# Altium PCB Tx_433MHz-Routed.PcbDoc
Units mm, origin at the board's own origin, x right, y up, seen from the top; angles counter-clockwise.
Board outline 100 x 50 mm, 4 copper layers (SIGNAL_1, SIGNAL_2, SIGNAL_3, SIGNAL_4), stack 1.58 mm thick; 34 components, 24 nets, 121 pads, 221 vias.
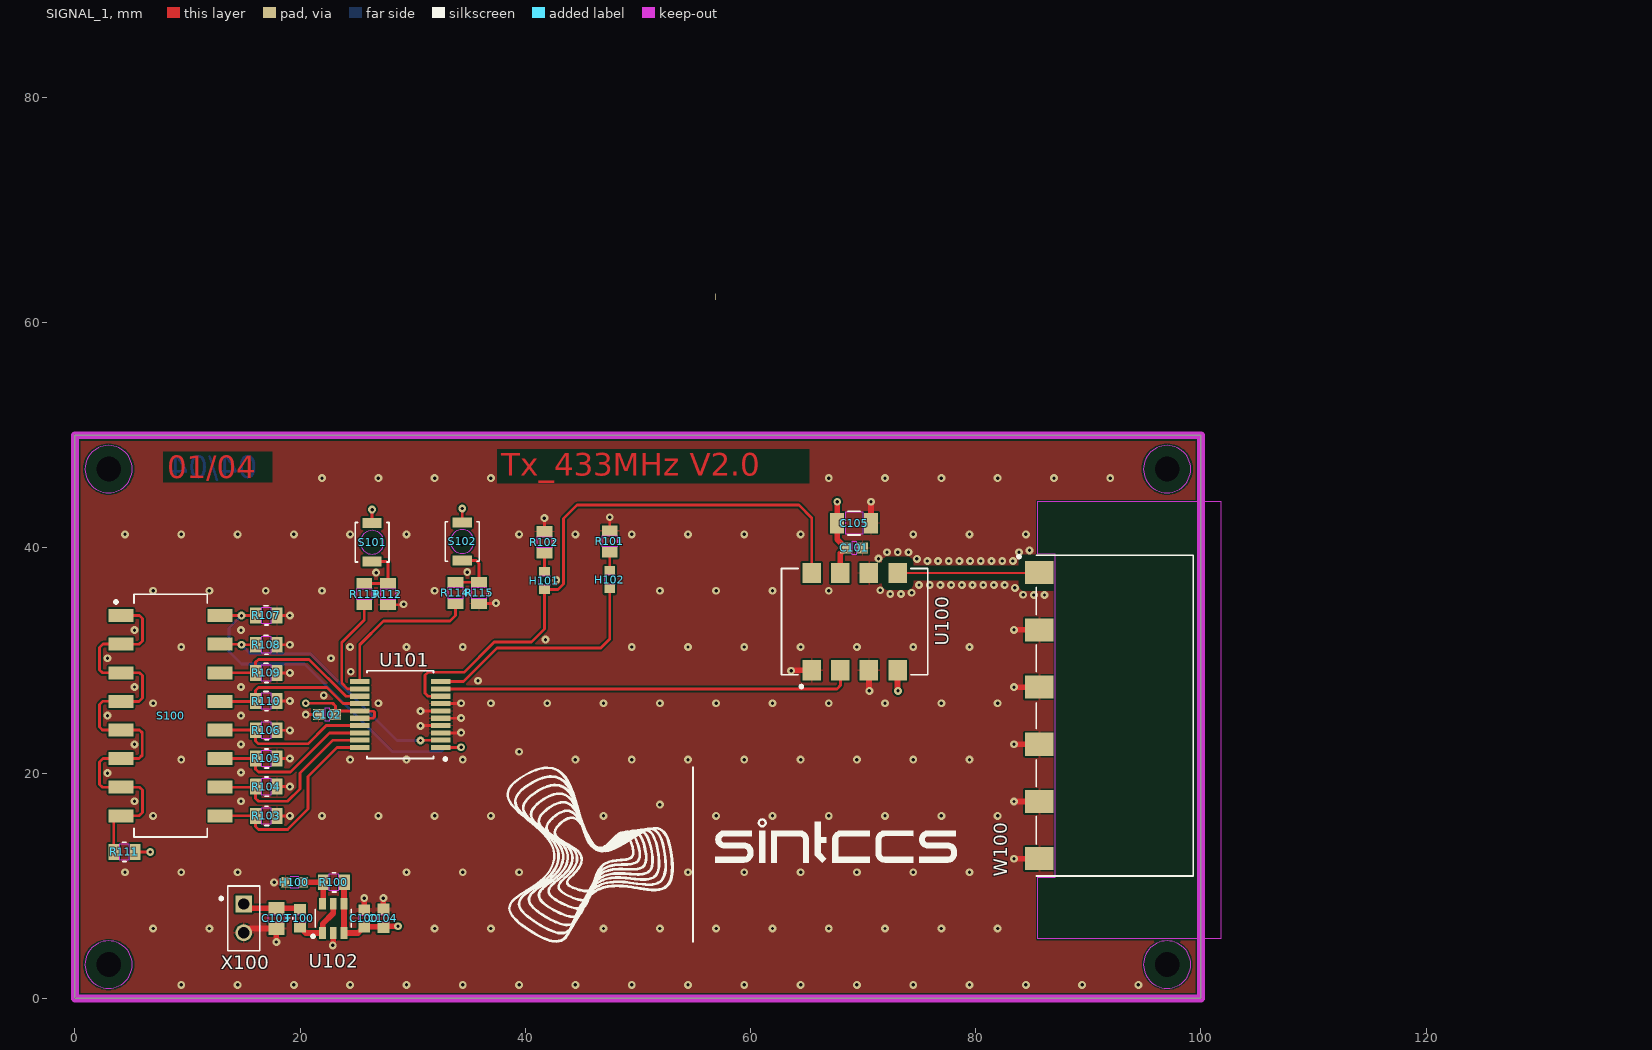
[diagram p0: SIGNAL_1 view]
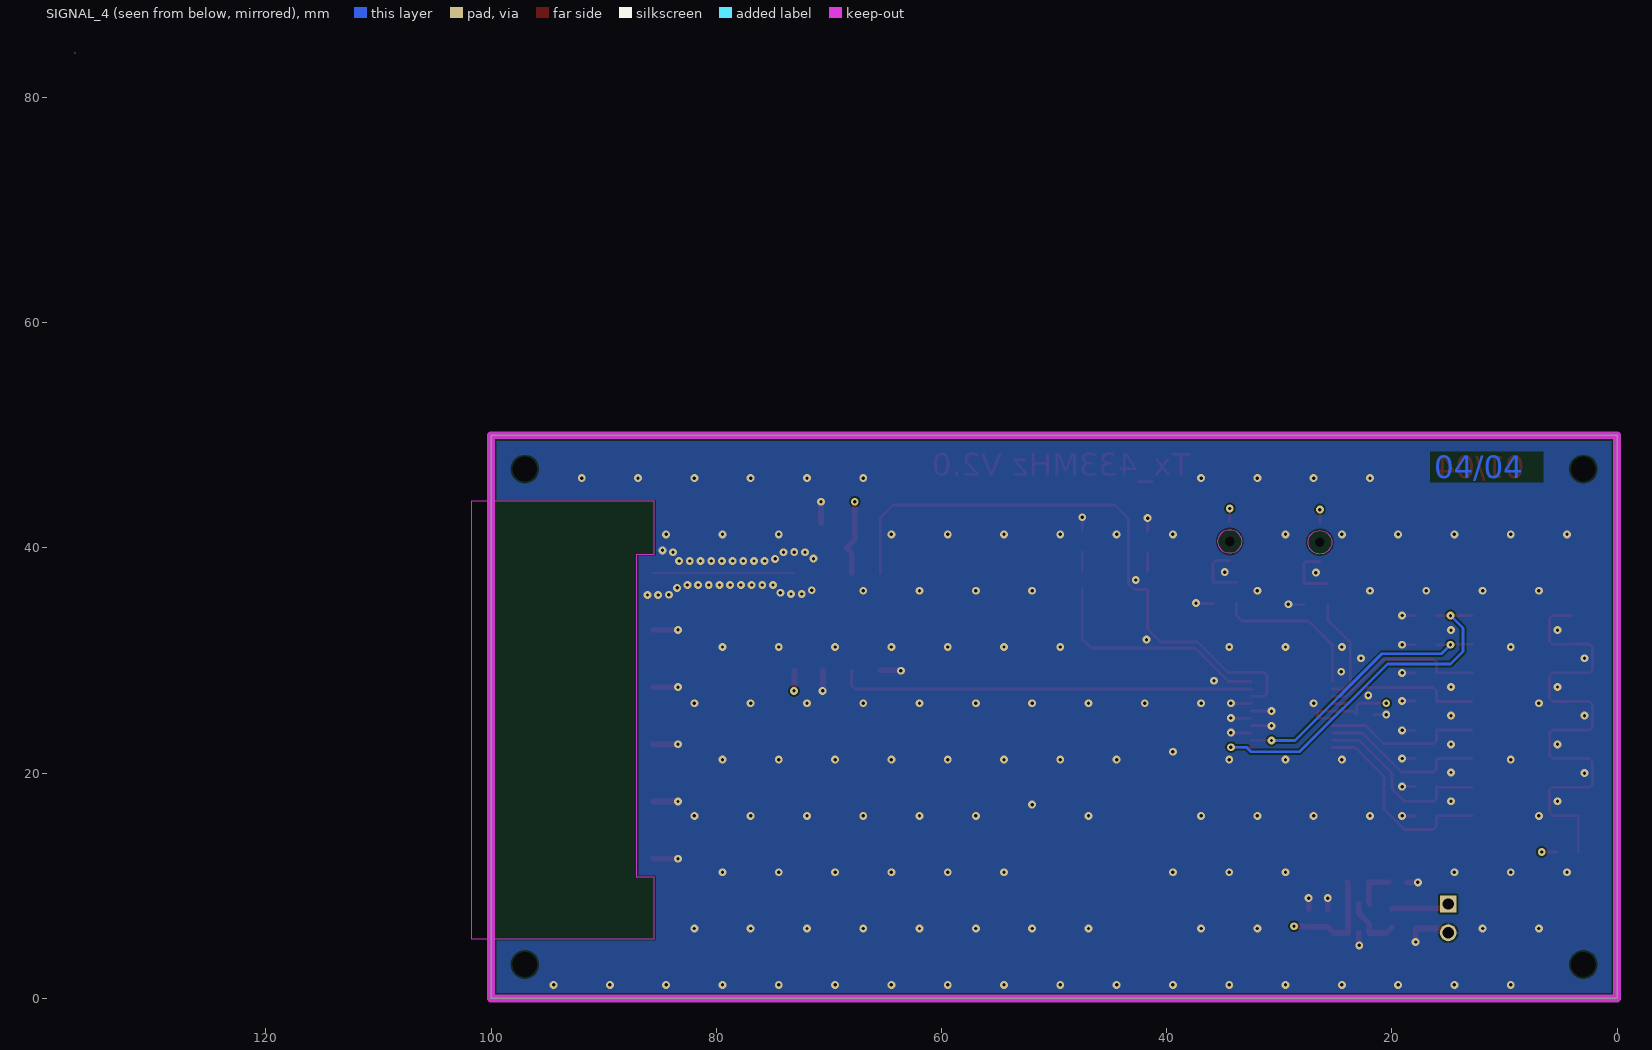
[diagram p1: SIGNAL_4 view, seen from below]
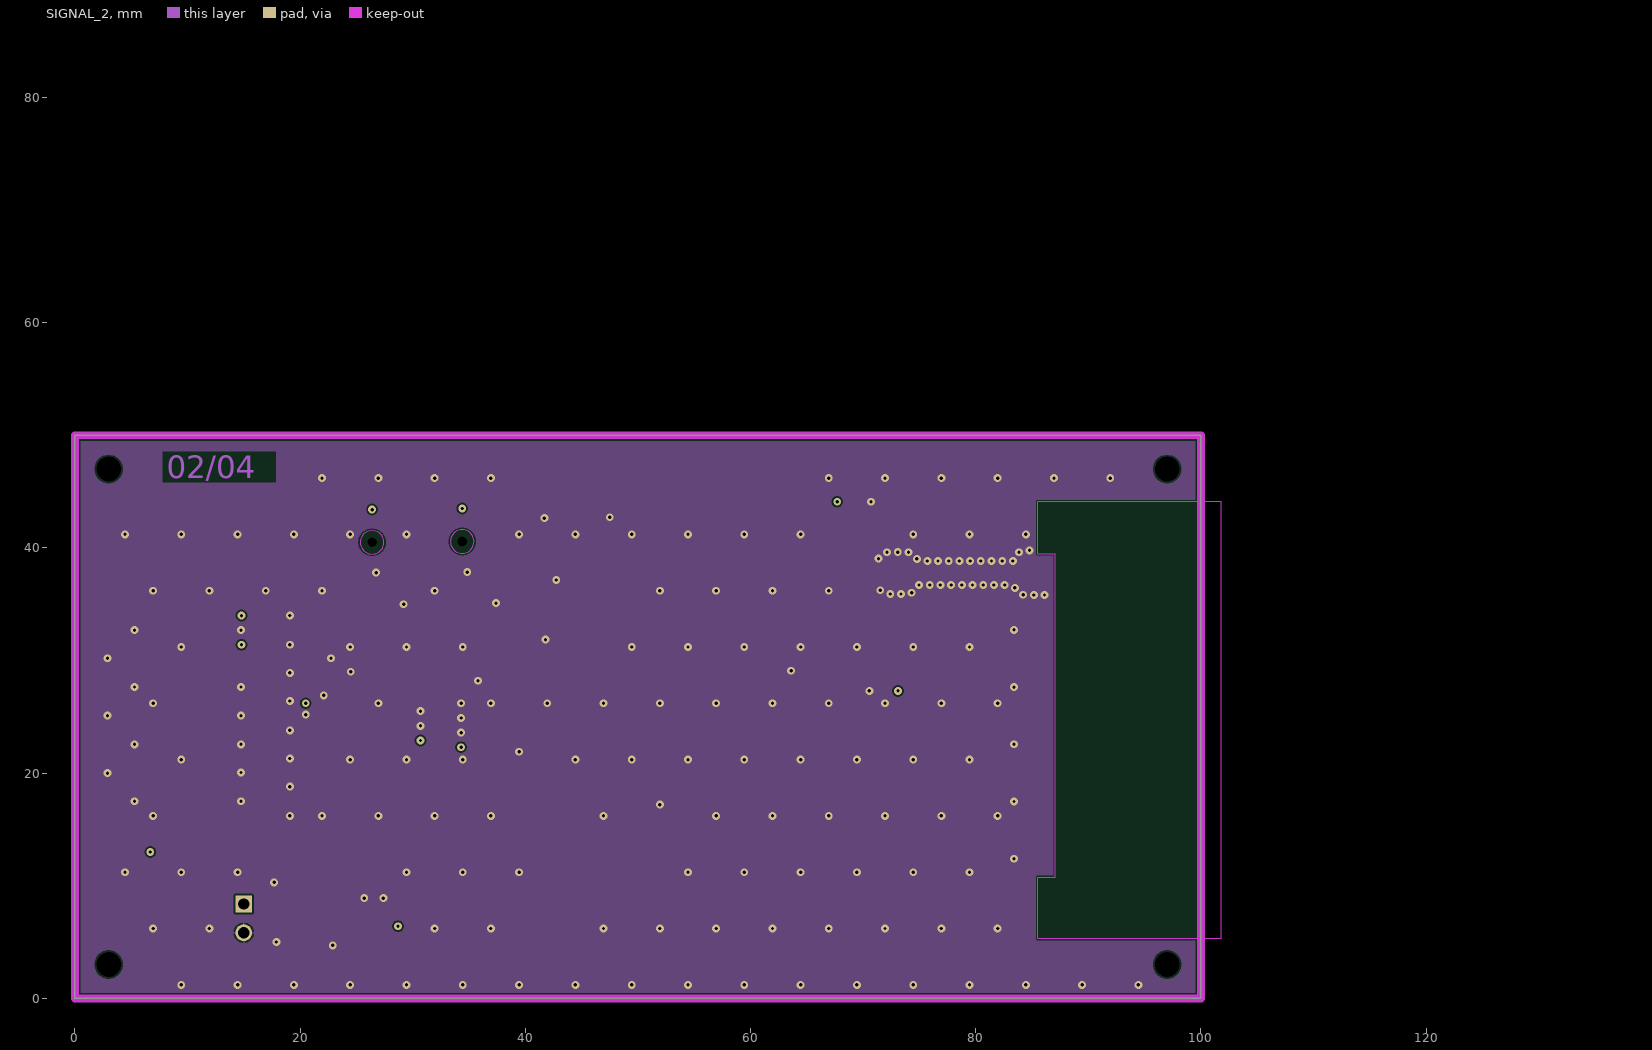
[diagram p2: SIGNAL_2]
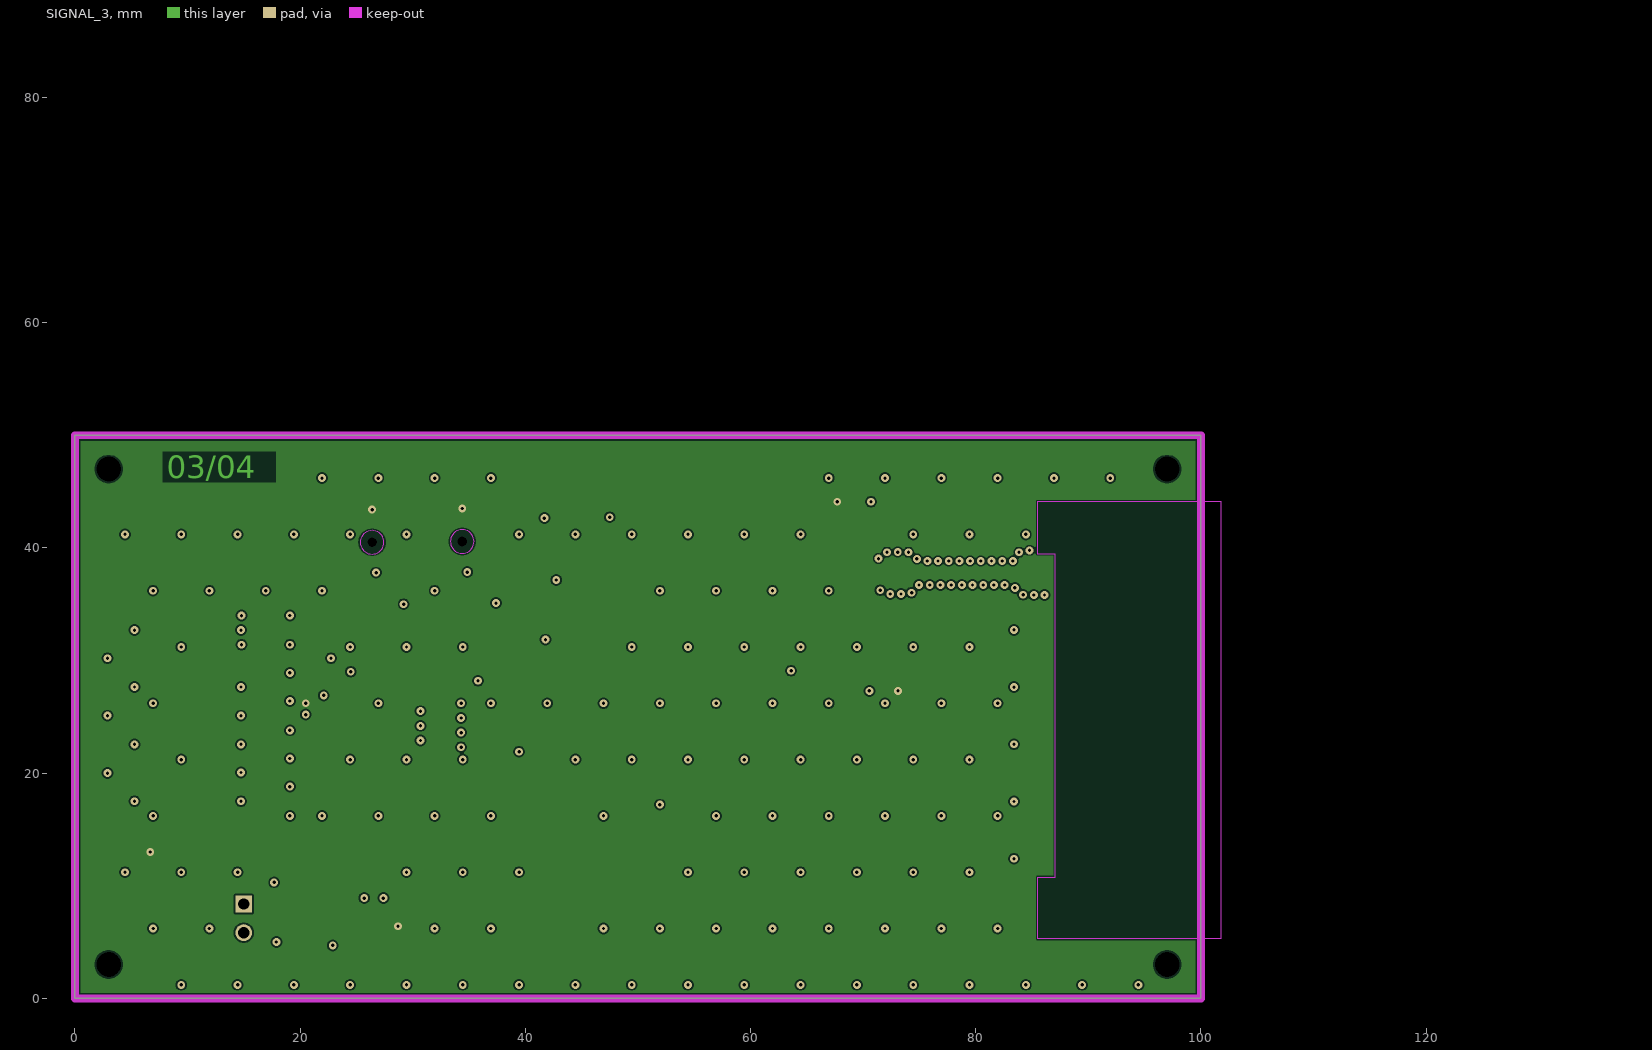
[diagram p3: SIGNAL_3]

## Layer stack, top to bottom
DIELECTRIC_1: solder mask 0.01, Dk 1
SIGNAL_1: signal copper 0.035
DIELECTRIC_3: prepreg 0.12, Dk 4.7
SIGNAL_2: signal copper 0.035
DIELECTRIC_5: prepreg 1.2, Dk 4.7
SIGNAL_3: signal copper 0.035
DIELECTRIC_7: prepreg 0.12, Dk 4.7
SIGNAL_4: signal copper 0.035
DIELECTRIC_9: solder mask 0.01, Dk 1

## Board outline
0,0 0,50 100,50 100,0

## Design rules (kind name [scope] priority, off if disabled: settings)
Clearance Clearance_50R [InNetClass('50R')] p1: gap=0.6 ignorepadtopadclearanceinfootprint=FALSE except(0.2: SMDPad-SMDPad)
Clearance [All] p2: gap=0.15 ignorepadtopadclearanceinfootprint=FALSE
ComponentClearance [All] p1: gap=0.1 collisioncheckmode=3 verticalgap=0.254 showdistances=FALSE
DiffPairsRouting [All] p1: maxlimit=0.254 minlimit=0.254 mostfreqgap=0.254 toplayer_minwidth=0.15 toplayer_maxwidth=0.3 toplayer_prefwidth=0.15 midlayer1_minwidth=0.15 midlayer1_maxwidth=0.3 midlayer1_prefwidth=0.15 midlayer2_minwidth=0.15 midlayer2_maxwidth=0.3 midlayer2_prefwidth=0.15 bottomlayer_minwidth=0.15 bottomlayer_maxwidth=0.3 bottomlayer_prefwidth=0.15 maxuncoupledlength=12.7
MinimumSolderMaskSliver [All] p1: minsoldermaskwidth=0.1
PolygonConnect [All] p1: thpad.connectstyle=Relief thpad.reliefconductorwidth=0.15 thpad.reliefentries=4 thpad.polygonreliefangle="90 Angle" thpad.airgapwidth=0.15 smdpad.connectstyle=Relief smdpad.reliefconductorwidth=0.15 smdpad.reliefentries=4 smdpad.polygonreliefangle="90 Angle" smdpad.airgapwidth=0.15 via.connectstyle=Direct via.reliefconductorwidth=0.127 via.reliefentries=2 via.polygonreliefangle="90 Angle" via.airgapwidth=0.152
RoutingVias [All] p1: holewidth=0.3 width=0.7 viastyle="Through Hole" minholewidth=0.3 minwidth=0.7 maxholewidth=0.3 maxwidth=0.7
SilkToSilkClearance [All] p1: silktosilkclearance=0.1
SolderMaskExpansion SolderMaskExpansion_Via [IsVia] p1: expansion=0.075 istentingtop=FALSE soldermaskfromhole=TRUE
SolderMaskExpansion [All] p2: expansion=0.1 istentingtop=FALSE
SupplyNets "Schematic Supply Nets_1" [InNet('GND_TX')] p1: voltage=0.000
SupplyNets "Schematic Supply Nets" [InNet('3V3_TX')] p2: voltage=0.000
UnRoutedNet [All] p1: checkbadconnections=TRUE
Width "Width for 50E_SE" [InNetClass('50R')] p1: maxlimit=0.2 minlimit=0.185 preferedwidth=0.2 toplayer_minwidth=0.2 bottomlayer_minwidth=0.2 impedanceprofiledriven=TRUE impedanceprofileid={877E34D1-77DC-4DEE-A0FB-207FE4FBDA97} impedanceprofilevalue=50.000000 minimp=50.000000 maximp=50.000000 favimp=50.000000
Width [All] p2: maxlimit=1 minlimit=0.15 preferedwidth=0.2
25 further rules are at their usual default settings.

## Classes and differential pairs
net class 50R: RF_TX
polygon class "\"(Inherited)\"": GND_RX_L02_P002

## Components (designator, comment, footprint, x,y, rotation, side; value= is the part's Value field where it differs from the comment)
C100 "C_0603_1608X90_GENERIC" CAPC1608X90N_0603_GENERIC 25.7,7.1 r90 top value=100nF
C101 "C_0603_1608X90_GENERIC" CAPC1608X90N_0603_GENERIC 69.2,40 r0 top value=100nF
C102 "C_0603_1608X90_GENERIC" CAPC1608X90N_0603_GENERIC 22.4,25.2 r180 top value=100nF
C103 "C_0805_2012X150_GENERIC" CAPC2012X150N_0805_GENERIC 17.9,7.1 r270 top value=1uF
C104 "CL10A226MP8NUNE" CAPC1608X105N 27.4,7.1 r90 top value=4.7uF
C105 "C_1206_3216X190_GENERIC" CAPC3216X190N_1206_GENERIC 69.2,42.2 r0 top value=10uF
F100 "0467XXXX" RESC1608X60N_0603_GENERIC 20,7.1 r270 top value=500mA
H100 "KP-1608SGC" LEDC1608X110N 19.5,10.3 r180 top
H101 "KP-1608SGC" LEDC1608X110N 41.7,37.1 r90 top
H102 "KP-1608SGC" LEDC1608X110N 47.5,37.175 r90 top
R100 "R_0805_2012X60_GENERIC" RESC2012X60N_0805_GENERIC 23,10.3 r180 top value=120R
R101 "R_0805_2012X60_GENERIC" RESC2012X60N_0805_GENERIC 47.5,40.575 r90 top value=120R
R102 "R_0805_2012X60_GENERIC" RESC2012X60N_0805_GENERIC 41.7,40.5 r90 top value=120R
R103 "R_0805_2012X60_GENERIC" RESC2012X60N_0805_GENERIC 17,16.2 r180 top value=100K
R104 "R_0805_2012X60_GENERIC" RESC2012X60N_0805_GENERIC 17,18.8 r180 top value=100K
R105 "R_0805_2012X60_GENERIC" RESC2012X60N_0805_GENERIC 17,21.3 r180 top value=100K
R106 "R_0805_2012X60_GENERIC" RESC2012X60N_0805_GENERIC 17,23.8 r180 top value=100K
R107 "R_0805_2012X60_GENERIC" RESC2012X60N_0805_GENERIC 17,34 r0 top value=100K
R108 "R_0805_2012X60_GENERIC" RESC2012X60N_0805_GENERIC 17,31.4 r0 top value=100K
R109 "R_0805_2012X60_GENERIC" RESC2012X60N_0805_GENERIC 17,28.9 r0 top value=100K
R110 "R_0805_2012X60_GENERIC" RESC2012X60N_0805_GENERIC 17,26.4 r0 top value=100K
R111 "R_0805_2012X60_GENERIC" RESC2012X60N_0805_GENERIC 4.4,13 r0 top value=1K
R112 "R_0805_2012X60_GENERIC" RESC2012X60N_0805_GENERIC 27.8,35.9 r90 top value=100K
R113 "R_0805_2012X60_GENERIC" RESC2012X60N_0805_GENERIC 25.7,35.9 r270 top value=1K
R114 "R_0805_2012X60_GENERIC" RESC2012X60N_0805_GENERIC 33.8,36 r270 top value=1K
R115 "R_0805_2012X60_GENERIC" RESC2012X60N_0805_GENERIC 35.9,36 r90 top value=100K
S100 "418121270808" WE_418121270808 8.5,25.1 r0 top
S101 "B3U_1000P_B" OMRON_B3U_1000P_B 26.4,40.5 r90 top
S102 "B3U_1000P_B" OMRON_B3U_1000P_B 34.402,40.57 r90 top
U100 "TXM-433-LR" LINX_TXM-433-LR 69.25,33.45 r90 top
U101 "LICAL-ENC-MS001" SOP65P780X200-20N 28.9,25.2 r180 top
U102 "MAX8881EU" SOT95P280X100-6N 22.95,7.1 r90 top
W100 "ANT-433-SP" LINX_ANT-433-SP 85.65,25.1 r270 top
X100 "M20_9770242" HARWIN_M20_9770242 15,7.1 r270 top

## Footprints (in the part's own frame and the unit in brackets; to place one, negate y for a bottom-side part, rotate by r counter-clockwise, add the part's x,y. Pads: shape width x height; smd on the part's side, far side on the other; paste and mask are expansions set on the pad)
CAPC1608X90N_0603_GENERIC [mm]
  rrect1% 1x1 smd paste-2539.97 mask-0.513: 1(-0.75,0) 2(0.75,0)
  SIGNAL_1 keep-out region: -0.22,-0.55 0.22,-0.55 0.22,0.55 -0.22,0.55
  body extent -1.5,-0.75 1.5,0.75, height 0.9
CAPC1608X105N [mm]
  rrect1% 1x1.05 smd paste-2539.97 mask-0.538: 1(-0.8,0) 2(0.8,0)
  SIGNAL_1 keep-out region: -0.3,-0.525 0.3,-0.525 0.3,0.525 -0.3,0.525
  body extent -1.55,-0.8 1.55,0.8, height 1.05
CAPC2012X150N_0805_GENERIC [mm]
  rrect1% 1.15x1.45 smd paste-2539.97 mask-0.738: 1(-0.9,0) 2(0.9,0)
  SIGNAL_1 keep-out region: -0.28,-0.78 0.28,-0.78 0.28,0.78 -0.28,0.78
  body extent -1.73,-1.05 1.73,1.05, height 1.5
CAPC3216X190N_1206_GENERIC [mm]
  rrect1% 1.25x1.8 smd paste-2539.97 mask-0.913: 1(-1.5,0) 2(1.5,0)
  SIGNAL_1 keep-out region: -0.8,-0.95 0.8,-0.95 0.8,0.95 -0.8,0.95
  silkscreen extent -0.55,-1.05 0.55,1.05, body extent -2.4,-1.15 2.4,1.15, height 1.9
HARWIN_M20_9770242 [mm]
  rrect1% 1.5x1.5 hole 1 paste-2539.97 mask-0.763: 1(-1.27,0)
  round 1.5 hole 1 paste-2539.97 mask-0.763: 2(1.27,0)
  silkscreen extent -2.87,-2.13 2.86,1.42, body extent -2.97,-1.52 2.96,1.52, height 8.38
LEDC1608X110N [mm]
  rrect1% 0.8x0.95 smd paste-2539.97 mask-0.488: 1(-0.8,0) 2(0.8,0)
  SIGNAL_1 keep-out region: -0.375,-0.5 0.375,-0.5 0.375,0.5 -0.375,0.5
  body extent -1.45,-0.75 1.45,0.75, height 0.65
LINX_ANT-433-SP [mm]
  rrect1% 2.05x2.55 smd paste-2539.97 mask-1.288: 1(-12.7,0) 2(-7.62,0) 3(-2.54,0) 4(2.54,0) 5(7.62,0) 6(12.7,0)
  SIGNAL_1 keep-out region: 14.35,-0.15 14.35,1.4 -14.35,1.4 -14.35,-0.15 -19.03,-0.15 -19.03,16.13 19.83,16.13 19.83,-0.15
  SIGNAL_2 keep-out region: 14.35,-0.15 14.35,1.4 -14.35,1.4 -14.35,-0.15 -19.03,-0.15 -19.03,16.13 19.83,16.13 19.83,-0.15
  SIGNAL_3 keep-out region: 14.35,-0.15 14.35,1.4 -14.35,1.4 -14.35,-0.15 -19.03,-0.15 -19.03,16.13 19.83,16.13 19.83,-0.15
  SIGNAL_4 keep-out region: 14.35,-0.15 14.35,1.4 -14.35,1.4 -14.35,-0.15 -19.03,-0.15 -19.03,16.13 19.83,16.13 19.83,-0.15
  silkscreen extent -14.25,-1.93 14.24,13.67, body extent -14.34,-1.55 14.34,13.77, height 1.5
LINX_TXM-433-LR [mm]
  rrect1% 1.8x1.65 smd paste-2539.97 mask-0.913: 1(-4.318,3.81) 2(-4.318,1.27) 3(-4.318,-1.27) 4(-4.318,-3.81) 5(4.318,-3.81) 6(4.318,-1.27) 7(4.318,1.27) 8(4.318,3.81)
  silkscreen extent -5.89,-6.5 4.72,6.5, body extent -5.5,-6.75 5.5,6.7, height 3.3
OMRON_B3U_1000P_B [mm]
  rrect1% 0.9x1.7 smd paste-2539.97 mask-0.863: 1(-1.7,0) 2(1.7,0)
  round 0 hole 0.85 unplated paste-2539.97 mask+0.925: ""(0,0)
  SIGNAL_1 keep-out region: 1.05,0 0.97,0.402 0.742,0.742 0.402,0.97 0,1.05 0,1.05 -0.402,0.97 -0.742,0.742 -0.97,0.402 -1.05,0 -1.05,0 -0.97,-0.402 -0.742,-0.742 -0.402,-0.97 0,-1.05 0,-1.05 0.402,-0.97 0.742,-0.742 0.97,-0.402 1.05,0
  SIGNAL_2 keep-out region: 1.05,0 0.97,0.402 0.742,0.742 0.402,0.97 0,1.05 0,1.05 -0.402,0.97 -0.742,0.742 -0.97,0.402 -1.05,0 -1.05,0 -0.97,-0.402 -0.742,-0.742 -0.402,-0.97 0,-1.05 0,-1.05 0.402,-0.97 0.742,-0.742 0.97,-0.402 1.05,0
  SIGNAL_3 keep-out region: 1.05,0 0.97,0.402 0.742,0.742 0.402,0.97 0,1.05 0,1.05 -0.402,0.97 -0.742,0.742 -0.97,0.402 -1.05,0 -1.05,0 -0.97,-0.402 -0.742,-0.742 -0.402,-0.97 0,-1.05 0,-1.05 0.402,-0.97 0.742,-0.742 0.97,-0.402 1.05,0
  SIGNAL_4 keep-out region: 1.05,0 0.97,0.402 0.742,0.742 0.402,0.97 0,1.05 0,1.05 -0.402,0.97 -0.742,0.742 -0.97,0.402 -1.05,0 -1.05,0 -0.97,-0.402 -0.742,-0.742 -0.402,-0.97 0,-1.05 0,-1.05 0.402,-0.97 0.742,-0.742 0.97,-0.402 1.05,0
  silkscreen extent -1.75,-1.5 1.75,1.5, body extent -2.4,-1.6 2.4,1.6, height 1.75
RESC1608X60N_0603_GENERIC [mm]
  rrect1% 0.95x1.05 smd paste-2539.97 mask-0.538: 1(-0.8,0) 2(0.8,0)
  SIGNAL_1 keep-out region: -0.3,-0.55 0.3,-0.55 0.3,0.55 -0.3,0.55
  silkscreen extent -0.08,-0.65 0.08,0.65, body extent -1.55,-0.8 1.55,0.8, height 0.6
RESC2012X60N_0805_GENERIC [mm]
  rrect1% 0.95x1.4 smd paste-2539.97 mask-0.713: 1(-0.95,0) 2(0.95,0)
  SIGNAL_1 keep-out region: -0.45,-0.7 0.45,-0.7 0.45,0.7 -0.45,0.7
  silkscreen extent -0.2,-0.85 0.15,0.85, body extent -1.7,-0.95 1.7,0.95, height 0.6
SOP65P780X200-20N [mm]
  rrect1% 1.75x0.45 smd paste-2539.97 mask-0.888: 1(-3.6,2.925) 2(-3.6,2.275) 3(-3.6,1.625) 4(-3.6,0.975) 5(-3.6,0.325) 6(-3.6,-0.325) 7(-3.6,-0.975) 8(-3.6,-1.625) 9(-3.6,-2.275) 10(-3.6,-2.925) 11(3.6,-2.925) 12(3.6,-2.275) 13(3.6,-1.625) 14(3.6,-0.975) 15(3.6,-0.325) 16(3.6,0.325) 17(3.6,0.975) 18(3.6,1.625) 19(3.6,2.275) 20(3.6,2.925)
  silkscreen extent -4.12,-3.9 2.95,4.08, body extent -4.75,-4 4.75,4, height 2
SOT95P280X100-6N [mm]
  rrect1% 1.05x0.6 smd paste-2539.97 mask-0.538: 1(-1.3,0.95) 2(-1.3,0) 3(-1.3,-0.95) 4(1.3,-0.95) 5(1.3,0) 6(1.3,0.95)
  silkscreen extent -1.72,-1.6 0.8,1.92, body extent -2.1,-1.7 2.1,1.7, height 1
WE_418121270808 [mm]
  rrect1% 2.2x1.15 smd paste-2539.97 mask-1.113: 1(-4.4,8.89) 2(-4.4,6.35) 3(-4.4,3.81) 4(-4.4,1.27) 5(-4.4,-1.27) 6(-4.4,-3.81) 7(-4.4,-6.35) 8(-4.4,-8.89) 9(4.4,-8.89) 10(4.4,-6.35) 11(4.4,-3.81) 12(4.4,-1.27) 13(4.4,1.27) 14(4.4,3.81) 15(4.4,6.35) 16(4.4,8.89)
  silkscreen extent -4.97,-10.78 3.25,10.78, body extent -5.75,-10.9 5.75,10.9, height 4.32

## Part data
C100 C101 C102: "100nF 25V 10%", Capacitance=100000, Dielectric=X7R, Manufacturer=MURATA, MPN=GRM188R71E104KA01D, Package=0603, Part Name="Ceramic chip capacitor 0603-1608x90, generic", Tolerance=10, Voltage=25V
C103: "1µF 25V 10%", Capacitance=1000000, Dielectric=X7R, Manufacturer=AVX, MPN=08053C105K4Z2A, Package=0805, Part Name="Ceramic chip capacitor 0805-2012x150, generic", Tolerance=10, Voltage=25V
C104: "4.7uF 25V 10%", Alternate Manufacturer=SAMSUNG, Alternate MPN=CL10A475KA8NQNC, Capacitance=4700000, Dielectric=X5R, Manufacturer=AVX, MPN=06033D475KAT2A, Package=0603, Part Name="CAP 22uF 10V 0603 X5R", Tolerance=10, Voltage=25V
C105: "10uF 25V 10%", Capacitance=10000000, Dielectric=X7R, Manufacturer=AVX, Max Temp=+125, Min Temp=-55, MPN=12063C106KAT2A, Package=1206, Part Name="Cheramic chip capacitor 1206-3216x190, generic", Tolerance=10, Voltage=25V
F100: "Thin film 0603 fuse very fast acting", Current=0.5, Manufacturer=LITTELFUSE, Max Temp=+90, Min Temp=-55, MPN=0467.500NRHF, Package=0603, Part Name="Thin film 0603 very fast acting", Voltage=32V
H100 H101 H102: "LED Green", Current=20mA, Manufacturer=KINGBRIGHT, MPN=APT-1608SGC, Package=0603, Part Name="SMD LED lamp, Green"
R100 R101 R102: "0.125W 5% 120R 50V", Manufacturer=YAGEO, MPN=RC0805JR-07120RL, Package=0805, Part Name="resistor_0805-2012x60 generic", Tolerance=5%
R103 R104 R105 R106 R107 R108 R109 R110 R112 R115: "0.125W 5% 100K 50V", Manufacturer=YAGEO, MPN=RC0805JR-07100KL, Package=0805, Part Name="resistor_0805-2012x60 generic", Tolerance=5%
R111 R113 R114: "Resistor_1K_1%_0805", Manufacturer=MULTICOMP, MPN=MCPWR05FTEW1001, Package=0805, Part Name="resistor_0805-2012x60 generic", Tolerance=1%
S100: "Dip Switch SPST 8 Position Surface Mount Slide (Standard) Actuator 25mA 24VDC", Current=25mA, Manufacturer="WURTH ELEKTRONIK", Max Temp=85, Min Temp=-40, Part Name="Dip Switch SPST 8 Position Surface Mount", Voltage=24
S101 S102: "Ultra-small Tactile Switch", Manufacturer=OMRON, Max Temp=0, MPN=B3U-1000P-B
U100: "LR Series Transmitter, Low Voltage, Low Power", Manufacturer="Linx Technologies", Max Temp=85, Min Temp=-40, Package=custom
U101: "MS Series Remote Controler Encoder, Low Voltage, Low Power", Manufacturer="LINX TECHNOLOGIES", Max Temp=85, Min Temp=-40, Package=SOP-20
U102: "Low Dropout Linear Regulator with enable and power good, 3.3V, 6 pin SOT23", Manufacturer=MAXIM, Max Temp=85, Min Temp=-40, MPN=MAX8881EUT33+T, Output Current=0.20A, Package=SOT23-6, Part Name="Low Dropout Linear Regulator, 6 pin SOT23"
W100: "433MHz 50 Ohm Antenna module", Manufacturer="Linx Technologies", Max Temp=130, Min Temp=-40, Package=custom
X100: "1x2 pin 2.54 mm pitch vertical header", Manufacturer=HARWIN, MPN=M20-9770242, Package=header, Part Name=STD_HEADER_1x2_2.54_THT

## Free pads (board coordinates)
  round 0 hole 2.2 unplated paste-2539.97 mask+1.6: ""(3,3) ""(3,47) ""(97,3) ""(97,47)
  round 0.025 smd far side paste-2539.97 mask-127: ""(136.95,83.95)

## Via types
v1: diameter 0.7, hole 0.3, SIGNAL_1 to SIGNAL_4, 221 vias

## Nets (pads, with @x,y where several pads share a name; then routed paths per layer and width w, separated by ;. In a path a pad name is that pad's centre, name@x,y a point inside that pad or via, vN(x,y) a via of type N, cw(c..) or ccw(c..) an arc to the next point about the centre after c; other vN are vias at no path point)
3V3_TX: C100.1 C101.1 C102.1 C104.1 C105.1 R100.1 R111.2 S101.2 S102.2 U100.4 U100.7 U101.15 U101.16 U102.3 U102.4 | length 30.9
  SIGNAL_1 w0.25: R111.2 v1(6.7,13) ; v1(20.5,26.2) 22.9,26.2 23.15,25.95 C102.1 23.475,25.525 U101.15 25.325,25.5 26.5,25.5 26.6,25.4 26.6,25 26.475,24.875 U101.16 ; S101.2 v1(26.4,43.4) ; S102.2@34.4,42.3 v1(34.4,43.5)
  SIGNAL_1 w0.5: R100.1 23.9,10.25 U102.4 U102.3 25.15,5.8 C100.1 27.35,6.35 C104.1 27.5,6.4 v1(28.7,6.4) ; v1(67.7,44.1) C105.1 67.7,40.75 C101.1 67.98,39.53 U100.7 ; U100.4 73.06,27.34 v1(73.1,27.3)
GND_TX: C100.2 C101.2 C102.2 C103.2 C104.2 C105.2 H100.2 R101.2 R102.2 R103.1 R104.1 R105.1 R106.1 R107.2 R108.2 R109.2 R110.2 R112.1 R115.1 U100.1 U100.3 U100.6 U101.3 U101.4 U101.5 U101.6 U101.7 U102.2 W100.2 W100.3 W100.4 W100.5 W100.6 X100.2 | length 50
  SIGNAL_1 w0.25: R103.1 v1(19.1,16.2) ; R104.1 v1(19.1,18.8) ; R105.1 v1(19.1,21.3) ; R106.1 v1(19.1,23.8) ; R110.2 v1(19.1,26.4) ; R109.2 v1(19.1,28.9) ; R108.2 v1(19.1,31.4) ; R107.2 v1(19.1,34) ; v1(20.5,25.2) C102.2 ; R112.1 29.15,34.95 v1(29.2,35) ; v1(30.7,24.2) 30.725,24.225 U101.4 ; v1(30.7,25.5) 30.725,25.525 U101.6 ; U101.3 34.275,23.575 v1(34.3,23.6) ; U101.5 34.275,24.875 v1(34.3,24.9) ; U101.7 34.275,26.175 v1(34.3,26.2) ; R115.1 37.35,35.05 v1(37.4,35.1) ; R102.2 v1(41.7,42.65) ; R101.2 v1(47.5,42.725)
  SIGNAL_1 w0.5: X100.2 15.37,6.2 C103.2 v1(17.9,5) ; v1(17.7,10.3) H100.2 ; v1(22.9,4.7) 22.95,4.75 U102.2 ; C100.2 v1(25.7,8.9) ; C104.2 v1(27.4,8.9) ; v1(63.608,29.092) 63.648,29.132 U100.1 ; U100.3 70.52,27.34 v1(70.56,27.3) ; C105.2 v1(70.7,44.1) ; v1(83.4,12.4) W100.6 ; v1(83.4,17.48) W100.5 ; v1(83.4,22.56) W100.4 ; v1(83.4,27.64) W100.3 ; v1(83.4,32.72) W100.2
  other v1: 9.45,1.2 14.45,1.2 19.45,1.2 24.45,1.2 29.45,1.2 34.45,1.2 39.45,1.2 44.45,1.2 49.45,1.2 54.45,1.2 59.45,1.2 64.45,1.2 69.45,1.2 74.45,1.2 79.45,1.2 84.45,1.2 89.45,1.2 94.45,1.2 6.95,6.2 11.95,6.2 31.95,6.2 36.95,6.2 46.95,6.2 51.95,6.2 56.95,6.2 61.95,6.2 66.95,6.2 71.95,6.2 76.95,6.2 81.95,6.2 4.45,11.2 9.45,11.2 14.45,11.2 29.45,11.2 34.45,11.2 39.45,11.2 54.45,11.2 59.45,11.2 64.45,11.2 69.45,11.2 74.45,11.2 79.45,11.2 6.95,16.2 21.95,16.2 26.95,16.2 31.95,16.2 36.95,16.2 46.95,16.2 56.95,16.2 61.95,16.2 66.95,16.2 71.95,16.2 76.95,16.2 81.95,16.2 51.95,17.2 5.3,17.5 14.75,17.5 2.9,20 14.75,20.05 9.45,21.2 24.45,21.2 29.45,21.2 34.45,21.2 44.45,21.2 49.45,21.2 54.45,21.2 59.45,21.2 64.45,21.2 69.45,21.2 74.45,21.2 79.45,21.2 39.45,21.9 5.3,22.55 14.75,22.55 2.9,25.1 14.75,25.1 6.95,26.2 26.95,26.2 36.95,26.2 41.95,26.2 46.95,26.2 51.95,26.2 56.95,26.2 61.95,26.2 66.95,26.2 71.95,26.2 76.95,26.2 81.95,26.2 22.1,26.9 5.3,27.65 14.75,27.65 35.8,28.2 24.5,29 2.9,30.2 22.75,30.2 9.45,31.2 24.45,31.2 29.45,31.2 34.45,31.2 49.45,31.2 54.45,31.2 59.45,31.2 64.45,31.2 69.45,31.2 74.45,31.2 79.45,31.2 41.8,31.85 5.3,32.7 14.75,32.7 85.161,35.816 86.111,35.816 84.211,35.837 72.414,35.909 73.364,35.909 74.308,36.018 6.95,36.2 11.95,36.2 16.95,36.2 21.95,36.2 31.95,36.2 51.95,36.2 56.95,36.2 61.95,36.2 66.95,36.2 71.523,36.24 83.482,36.446 74.967,36.702 75.917,36.702 76.867,36.702 77.817,36.702 78.767,36.702 79.717,36.702 80.667,36.702 81.617,36.702 82.567,36.702 42.75,37.15 26.75,37.8 34.85,37.85 75.703,38.834 76.653,38.834 77.603,38.834 78.553,38.834 79.503,38.834 80.453,38.834 81.403,38.834 82.353,38.834 83.303,38.834 74.772,39.023 71.363,39.053 72.127,39.619 73.077,39.627 74.027,39.612 83.847,39.613 84.781,39.784 4.45,41.2 9.45,41.2 14.45,41.2 19.45,41.2 24.45,41.2 29.45,41.2 39.45,41.2 44.45,41.2 49.45,41.2 54.45,41.2 59.45,41.2 64.45,41.2 74.45,41.2 79.45,41.2 84.45,41.2 21.95,46.2 26.95,46.2 31.95,46.2 36.95,46.2 66.95,46.2 71.95,46.2 76.95,46.2 81.95,46.2 86.95,46.2 91.95,46.2
NetC103_1: C103.1 F100.1 X100.1 | length 5.2
  SIGNAL_1 w0.5: X100.1 15.37,8 C103.1 19.9,8 F100.1
NetF100_2: F100.2 U102.1 U102.5 | length 5.2
  SIGNAL_1 w0.5: F100.2 20.5,5.8 U102.1 22,6.6 22.95,7.55 U102.5
NetH100_1: H100.1 R100.2 U102.6 | length 3.7
  SIGNAL_1 w0.5: H100.1 R100.2 22.05,8.45 U102.6
NetH101_1: H101.1 U100.8 U101.8 | length 54.5
  SIGNAL_1 w0.25: U101.8 31.375,26.825 31.1,27.1 31.1,28.7 31.35,28.95 34.55,28.95 37.25,31.65 40.55,31.65 41.7,32.8 H101.1 42.9,36.3 43.4,36.8 43.4,42.6 44.6,43.8 64.3,43.8 65.44,42.66 U100.8
NetH101_2: H101.2 R102.1 | length 1.6
  SIGNAL_1 w0.25: H101.2 R102.1
NetH102_1: H102.1 U101.10 | length 21
  SIGNAL_1 w0.25: U101.10 34.525,28.125 37.5,31.1 46.7,31.1 47.5,31.9 H102.1
NetH102_2: H102.2 R101.1 | length 1.6
  SIGNAL_1 w0.25: H102.2 R101.1
NetR103_2: R103.2 S100.9 U101.20 | length 18.2
  SIGNAL_1 w0.25: S100.9 16.04,16.21 R103.2 16.05,15.25 16.3,15 18.9,15 20.7,16.8 20.7,19.7 23.275,22.275 U101.20
NetR104_2: R104.2 S100.10 U101.19 | length 16.6
  SIGNAL_1 w0.25: S100.10 16,18.75 R104.2 16.05,17.75 16.3,17.5 18.9,17.5 20,18.6 20,20 22.925,22.925 U101.19
NetR105_2: R105.2 S100.11 U101.18 | length 14.9
  SIGNAL_1 w0.25: S100.11 16.04,21.29 R105.2 16.05,20.35 16.3,20.1 19.15,20.1 22.625,23.575 U101.18
NetR106_2: R106.2 S100.12 U101.17 | length 14.1
  SIGNAL_1 w0.25: S100.12 16.02,23.83 R106.2 16.05,22.85 16.3,22.6 20.7,22.6 22.325,24.225 U101.17
NetR107_1: R107.1 S100.16 U101.1 | length 33.1
  SIGNAL_1 w0.25: S100.16 v1(14.8,33.99) 16.04,33.99 R107.1 ; U101.1 34.275,22.275 v1(34.3,22.3)
  SIGNAL_4 w0.25: v1(14.8,33.99) 13.7,32.89 13.7,30.8 14.8,29.7 20.4,29.7 28.2,21.9 32.5,21.9 32.9,22.3 v1(34.3,22.3)
NetR108_1: R108.1 S100.15 U101.2 | length 24.4
  SIGNAL_1 w0.25: S100.15 14.65,31.45 14.7,31.4 v1(14.8,31.4) R108.1 ; v1(30.7,22.9) 30.725,22.925 U101.2
  SIGNAL_4 w0.25: v1(14.8,31.4) 15.6,30.6 20.9,30.6 28.6,22.9 v1(30.7,22.9)
NetR109_1: R109.1 S100.14 U101.13 | length 14.8
  SIGNAL_1 w0.25: S100.14 16.04,28.91 R109.1 16.05,29.85 16.3,30.1 20.8,30.1 24.075,26.825 U101.13
NetR110_1: R110.1 S100.13 U101.14 | length 14.1
  SIGNAL_1 w0.25: S100.13 16.02,26.37 R110.1 16.05,27.35 16.3,27.6 22.4,27.6 23.825,26.175 U101.14
NetR111_1: R111.1 S100.1 S100.2 S100.3 S100.4 S100.5 S100.6 S100.7 S100.8 | length 46.1
  SIGNAL_1 w0.25: R111.1 3.45,16.21 S100.8 5.71,16.21 6,16.5 6,18.5 5.75,18.75 S100.7 2.45,18.75 2.2,19 2.2,21 2.5,21.3 S100.6@4.09,21.3 ; S100.4@4.09,26.38 4.08,26.39 2.49,26.39 2.19,26.09 2.19,24.09 2.44,23.84 4.09,23.84 5.74,23.84 5.99,23.59 5.99,21.59 5.7,21.3 S100.6@4.09,21.3 ; S100.6 S100.6@4.09,21.3 ; S100.4 5.71,26.37 6,26.66 6,28.66 5.75,28.91 S100.3 2.45,28.91 2.2,29.16 2.2,31.16 2.5,31.46 4.09,31.46 S100.2 5.71,31.45 6,31.74 6,33.74 5.75,33.99 S100.1
NetR112_2: R112.2 R113.1 S101.1 | length 5.4
  SIGNAL_1 w0.25: R113.1 R112.2 27.8,38.65 27.65,38.8 S101.1
NetR113_2: R113.2 U101.12 | length 9.6
  SIGNAL_1 w0.25: U101.12 24.225,27.475 23.7,28 23.7,31.6 25.7,33.6 R113.2
NetR114_1: R114.1 R115.2 S102.1 | length 5.4
  SIGNAL_1 w0.25: R114.1 R115.2 35.9,38.622 35.652,38.87 S102.1
NetR114_2: R114.2 U101.11 | length 13.9
  SIGNAL_1 w0.25: U101.11 25.3,31.4 27.4,33.5 33.3,33.5 33.8,34 R114.2
NetU100_2: U100.2 U101.9 | length 37
  SIGNAL_1 w0.25: U101.9 67.675,27.475 68,27.8 67.98,27.82 U100.2
RF_TX: U100.5 W100.1 | length 12.6
  SIGNAL_1 w0.2: U100.5 85.618,37.768 W100.1
pads on no net: S101. S102.

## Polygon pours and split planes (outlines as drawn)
GND_TX on SIGNAL_2 "02-GND_TX" (solid, remove dead copper, pour order 0): 0,0 100,0 100,50 0,50
3V3_TX on SIGNAL_3 "03-3V3_TX" (solid, remove dead copper, pour order 1): 0,0 100,0 100,50 0,50
GND_TX on SIGNAL_1 "01-GND_TX" (solid, remove dead copper, pour order 2): 0,0 100,0 100,50 0,50
GND_TX on SIGNAL_4 "04-GND_TX" (solid, remove dead copper, pour order 3): 0,0 100,0 100,50 0,50

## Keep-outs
SIGNAL_1:
  region: 99.1,3 ccw(c97,3) 97,5.1 ccw(c97,3) 94.9,3 ccw(c97,3) 97,0.9 ccw(c97,3)
  region: 5.1,3 ccw(c3,3) 3,5.1 ccw(c3,3) 0.9,3 ccw(c3,3) 3,0.9 ccw(c3,3)
  region: 5.1,47 ccw(c3,47) 3,49.1 ccw(c3,47) 0.9,47 ccw(c3,47) 3,44.9 ccw(c3,47)
  region: 99.1,47 ccw(c97,47) 97,49.1 ccw(c97,47) 94.9,47 ccw(c97,47) 97,44.9 ccw(c97,47)
  region: 99.1,47 ccw(c97,47) 97,49.1 ccw(c97,47) 94.9,47 ccw(c97,47) 97,44.9 ccw(c97,47)
Keep-Out Layer:
  lines w0.7: 0,50 100,50 ; 0,50 0,0 100,0 100,50 ; 0,50 100,50

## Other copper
SIGNAL_1:
  pour cut-out: 99.1,3 ccw(c97,3) 97,5.1 ccw(c97,3) 94.9,3 ccw(c97,3) 97,0.9 ccw(c97,3)
  pour cut-out: 5.1,3 ccw(c3,3) 3,5.1 ccw(c3,3) 0.9,3 ccw(c3,3) 3,0.9 ccw(c3,3)
  pour cut-out: 5.1,47 ccw(c3,47) 3,49.1 ccw(c3,47) 0.9,47 ccw(c3,47) 3,44.9 ccw(c3,47)
  pour cut-out: 99.1,47 ccw(c97,47) 97,49.1 ccw(c97,47) 94.9,47 ccw(c97,47) 97,44.9 ccw(c97,47)
  pour cut-out: 99.1,47 ccw(c97,47) 97,49.1 ccw(c97,47) 94.9,47 ccw(c97,47) 97,44.9 ccw(c97,47)
  text "Tx_433MHz V2.0" at 37.866,46.425 h2
  text "01/04" at 8.186,46.175 h2
  text "Layer 01/04 Top" at 33.324,-23.065 h2
SIGNAL_2:
  text "02/04" at 8.156,46.175 h2
  text "Layer 02/04" at 33.324,-23.065 h2
SIGNAL_3:
  text "03/04" at 8.156,46.175 h2
  text "Layer 03/04" at 33.324,-23.065 h2
SIGNAL_4:
  text "04/04" at 16.264,46.175 h2
  text "Layer 04/04 Bottom" at 69.073,-23.065 h2

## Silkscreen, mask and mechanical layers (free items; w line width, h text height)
Top Overlay:
  drawing of 47 lines, arcs and shapes, not listed
  text "SILKSCREEN TOP" at 66.497,-23.235 h2
DIELECTRIC_1:
  text "SOLDERMASK TOP" at 33.334,-23.005 h2
DIELECTRIC_9:
  text "SOLDERMASK BOTTOM" at 33.344,-23.005 h2
Top Assembly:
  text "U100" at 67.25,32.85 h1
  text "U101" at 27.35,25.05 h1
  text "W100" at 90.5,24.7 h1
  text "U102" at 22.3,7 h0.5
  text "X100" at 15.35,5.5 h1 r90
  text "Assembly Drawing Top" at 33.604,-23.29 h2
Default User Layer:
  lines w0.025: 1,1 1,49 ; 1,1 85,1 ; 1,1 1,49 ; 1,1 85,1 ; 1,49 85,49 ; 1,49 85,49 ; 1,49 85,49 ; 1,49 85,49 ; 85,1 85,49 ; 85,1 85,49 ; 85,1 85,49 ; 85,1 85,49
VSCORE_DETAIL:
  lines w0.1: 0,50 100,50
  text "VSCORE DETAIL" at 33.334,-23.005 h2
Panel Dimension:
  circle w0.2: c3,47 r1.1
  circle w0.2: c97,47 r1.1
  circle w0.2: c97,47 r1.1
  circle w0.2: c97,3 r1.1
  circle w0.2: c3,3 r1.1
  lines w0.2: 0,50 100,50 ; 0,50 0,0 100,0 100,50 ; 0,50 100,50
  text "Panel Drawing" at 33.864,-23.295 h2
Single Board Dimensions:
  circle w0.2: c3,3 r1.1
  circle w0.2: c97,3 r1.1
  circle w0.2: c97,47 r1.1
  circle w0.2: c97,47 r1.1
  circle w0.2: c3,47 r1.1
  lines w0.2: 0,50 100,50 ; 0,50 0,0 100,0 100,50 ; 0,50 100,50
  text "Single Board Dimensions" at 33.334,-23.005 h2
TitleBlock_Mirrored:
  drawing of 102 lines, arcs and shapes, not listed
  text "PROJECT:" at 76.049,-13.849 h0.76
  text "TX & RX 433MHZ UT Scintilla Workshop" at 68.987,-15.551 h2
  text "DRAWN BY:" at 76.049,-17.659 h0.76
  text "Lesley Snijder/Henk Mengerink" at 69.191,-19.281 h2
  text "LAYER:" at 76.049,-21.469 h0.76
  text "DATE:" at 16.613,-25.279 h0.76
  text "REV:" at 26.519,-25.279 h0.76
  text "DWG NO:" at 76.049,-25.279 h0.76
  text "30 Apr2021" at 12.549,-27.041 h2
  text "2.0" at 23.217,-27.041 h2
  text "THE INFORMATION HEREIN IS PROPRIETARY TO YOUR DESIGN COMPANY" at 111.709,-27.628 h0.64
TittleBlock:
  drawing of 102 lines, arcs and shapes, not listed
  text "PROJECT:" at 26.889,-13.869 h0.76
  text "TX & RX 433MHZ UT Scintilla Workshop" at 33.747,-15.531 h2
  text "DRAWN BY:" at 26.889,-17.679 h0.76
  text "Lesley Snijder/Henk Mengerink" at 33.747,-19.301 h2
  text "LAYER:" at 26.889,-21.489 h0.76
  text "DWG NO:" at 26.889,-25.299 h0.76
  text "REV:" at 76.419,-25.299 h0.76
  text "DATE:" at 86.325,-25.299 h0.76
  text "2.0" at 79.721,-27.061 h2
  text "30 Apr 2021" at 90.389,-27.061 h2
  text "THE INFORMATION HEREIN IS PROPRIETARY TO YOUR DESIGN COMPANY" at -8.771,-27.648 h0.64
Drill Drawing:
  lines w0.15: -22.95,-45.95 134.55,-45.95 ; -22.95,-39.95 134.55,-39.95 ; -22.95,-62.45 -22.95,-30.95 134.55,-30.95 134.55,-62.45 -22.95,-62.45
  text "E" at 3,96 h2
  text "E" at 97,96 h2
  text "A" at 66.42,91.24 h2
  text "A" at 71.68,91.24 h2
  text "A" at 43.09,90.65 h2
  text "A" at 56.5,90.65 h2
  text "A" at 31,88.55 h2
  text "A" at 6.98,88.49 h2
  text "D" at 43.1,88 h2
  text "D" at 56.5,88 h2
  text "A" at 49.85,87.74 h2
  text "A" at 38.54,86.13 h2
  text "A" at 18.66,85.93 h2
  text "A" at 78.64,85 h2
  text "A" at 82.3,84.67 h2
  text "A" at 41.17,84.05 h2
  text "A" at 54.57,84.05 h2
  text "A" at 83.76,81.72 h2
  text "A" at 78.92,80.83 h2
  text "A" at 58.77,79.72 h2
  text "A" at 51.12,78.4 h2
  text "A" at 54.98,78.4 h2
  text "A" at 65.43,76.73 h2
  text "A" at 70.52,76.73 h2
  text "A" at 73.05,76.73 h2
  text "A" at 6.89,76.65 h2
  text "A" at 83.76,76.64 h2
  text "A" at 51.12,75.85 h2
  text "A" at 54.98,75.85 h2
  text "A" at 68.6,75.09 h2
  text "A" at 30.84,74.25 h2
  text "A" at 56.5,74.18 h2
  text "A" at 51.12,73.3 h2
  text "A" at 79.23,73.15 h2
  text "A" at 83.76,71.56 h2
  text "A" at 51.12,70.8 h2
  text "A" at 79.23,70.6 h2
  text "A" at 65.64,70.55 h2
  text "A" at 68.69,69.57 h2
  text "A" at 54.9,69.55 h2
  text "A" at 18.54,68.46 h2
  text "A" at 57.4,68.46 h2
  text "A" at 65.65,68.25 h2
  text "A" at 51.12,68.2 h2
  text "A" at 69.01,67.28 h2
  text "A" at 83.76,66.48 h2
  text "A" at 69.01,65.96 h2
  text "A" at 51.12,65.7 h2
  text "A" at 70.96,64.65 h2
  text "A" at 79.05,64.65 h2
  text "A" at 69.7,64.39 h2
  text "A" at 51.12,63.15 h2
  text "A" at 6.78,62.23 h2
  text "C" at 60.23,61.67 h2
  text "A" at 83.76,61.4 h2
  text "A" at 51.12,60.6 h2
  text "A" at 64.84,60.6 h2
  text "A" at 30.67,59.95 h2
  text "C" at 60.23,59.13 h2
  text "A" at 64.85,59.1 h2
  text "A" at 78.85,57.44 h2
  text "E" at 3,52 h2
  text "E" at 97,52 h2
  text "E" at 3,46 h2
  text "E" at 97,46 h2
  text "A" at 4.63,41.86 h2
  text "A" at 29.48,41.21 h2
  text "A" at 66.43,40.71 h2
  text "C" at 45.53,40.68 h2
  text "C" at 48.07,40.68 h2
  text "A" at 53.83,40.7 h2
  text "B" at 3.055,38.58 h2
  text "B" at 18.295,38.58 h2
  text "A" at 47.53,38 h2
  text "A" at 34.53,37.67 h2
  text "A" at 50.78,36.1 h2
  text "A" at 46.55,36.06 h2
  text "B" at 3.055,36.04 h2
  text "B" at 18.295,36.04 h2
  text "A" at 46.56,34.91 h2
  text "A" at 77.44,34.69 h2
  text "A" at 82.12,34.69 h2
  text "A" at 50.78,34.2 h2
  text "A" at 74.65,34.16 h2
  text "A" at 34.53,33.87 h2
  text "B" at 3.055,33.5 h2
  text "B" at 18.295,33.5 h2
  text "A" at 39.37,32.92 h2
  text "A" at 42.26,32.6 h2
  text "A" at 50.79,31.77 h2
  text "A" at 83.11,31.62 h2
  text "A" at 39.37,31.02 h2
  text "B" at 3.055,30.96 h2
  text "B" at 18.295,30.96 h2
  text "A" at 51.5,29.2 h2
  text "A" at 78.52,28.46 h2
  text "B" at 3.055,28.42 h2
  text "B" at 18.295,28.42 h2
  text "A" at 37.98,28.32 h2
  text "A" at 26.55,26.7 h2
  text "A" at 83.11,26.54 h2
  text "A" at 30.1,26.47 h2
  text "A" at 51.5,26.21 h2
  text "A" at 25.5,26 h2
  text "A" at 14.55,24.94 h2
  text "C" at 42,23.78 h2
  text "A" at 30.78,23.09 h2
  text "A" at 37.97,23.1 h2
  text "A" at 51.12,22.25 h2
  text "B" at 2.905,21.78 h2
  text "B" at 18.145,21.78 h2
  text "A" at 83.11,21.46 h2
  text "C" at 42,21.24 h2
  text "A" at 34.53,19.89 h2
  text "B" at 2.905,19.24 h2
  text "B" at 18.145,19.24 h2
  text "C" at 42,18.7 h2
  text "A" at 48.38,18.56 h2
  text "B" at 2.905,16.7 h2
  text "B" at 18.145,16.7 h2
  text "A" at 48.38,16.66 h2
  text "A" at 83.11,16.38 h2
  text "C" at 42,16.16 h2
  text "A" at 34.53,16.08 h2
  text "A" at 63.03,15.82 h2
  text "A" at 39.39,15.15 h2
  text "A" at 60.27,14.54 h2
  text "B" at 2.905,14.16 h2
  text "B" at 18.145,14.16 h2
  text "A" at 78.41,14.04 h2
  text "A" at 66.43,13.85 h2
  text "C" at 42,13.62 h2
  text "A" at 39.37,13.24 h2
  text "A" at 60.24,12.92 h2
  text "A" at 49.35,12.9 h2
  text "A" at 51.85,11.73 h2
  text "B" at 2.905,11.62 h2
  text "B" at 18.145,11.62 h2
  text "A" at 63.25,11.59 h2
  text "A" at 83.11,11.3 h2
  text "C" at 42,11.08 h2
  text "A" at 63.39,10.63 h2
  text "A" at 39.19,9.84 h2
  text "A" at 63.39,9.31 h2
  text "A" at 66.49,8.88 h2
  text "A" at 58.79,8.73 h2
  text "A" at 26,8.7 h2
  text "A" at 30.05,8.7 h2
  text "C" at 42,8.54 h2
  text "A" at 37.1,7.14 h2
  text "A" at 52.5,6.8 h2
  text "D" at 55.15,6.8 h2
  text "A" at 13.66,6.75 h2
  text "C" at 42,6 h2
  text "A" at 30.94,5.5 h2
  text "E" at 3,2 h2
  text "E" at 97,2 h2
  text "Through Holes" at 47.75,-34.7 h1.5
  text "All Drills (unless specified) +/- 0.1000 (MM)" at 25.675,-37.7 h1.5
  text "Symbol" at -19.208,-43.7 h1.5
  text "Diameter" at 1.834,-43.7 h1.5
  text "Tolerance" at 29.561,-43.7 h1.5
  text "Plated" at 52.798,-43.7 h1.5
  text "HoleName" at 85.805,-43.7 h1.5
  text "Quantity" at 120.337,-43.7 h1.5
  text "A" at -15.45,-48.2 h1.5
  text "0.3000" at 3.379,-48.2 h1.5
  text "+/- 0.1000" at 29.132,-48.2 h1.5
  text "Yes" at 55.01,-48.2 h1.5
  text "Rnd 0.30 +/-Tol 0.10" at 77.714,-48.2 h1.5
  text "114" at 124.046,-48.2 h1.5
  text "B" at -15.45,-51.2 h1.5
  text "0.9000" at 3.379,-51.2 h1.5
  text "+/- 0.1000" at 29.132,-51.2 h1.5
  text "Yes" at 55.01,-51.2 h1.5
  text "Rnd 0.90 +/-Tol 0.10" at 77.714,-51.2 h1.5
  text "20" at 124.766,-51.2 h1.5
  text "C" at -15.45,-54.2 h1.5
  text "1.0000" at 3.402,-54.2 h1.5
  text "+/- 0.1000" at 29.132,-54.2 h1.5
  text "Yes" at 55.01,-54.2 h1.5
  text "Rnd 1.00 +/-Tol 0.10" at 77.74,-54.2 h1.5
  text "12" at 124.78,-54.2 h1.5
  text "D" at -15.45,-57.2 h1.5
  text "0.8500" at 3.385,-57.2 h1.5
  text "+/- 0.1000" at 29.132,-57.2 h1.5
  text "No" at 55.767,-57.2 h1.5
  text "Rnd 0.85 +/-Tol 0.10 Non-Plated" at 69.797,-57.2 h1.5
  text "3" at 125.55,-57.2 h1.5
  text "E" at -15.45,-60.2 h1.5
  text "2.2000" at 3.379,-60.2 h1.5
  text "+/- 0.1000" at 29.132,-60.2 h1.5
  text "No" at 55.767,-60.2 h1.5
  text "Rnd 2.20 +/-Tol 0.10 Non-Plated" at 69.79,-60.2 h1.5
  text "8" at 125.55,-60.2 h1.5

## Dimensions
0,50 to 3,1.9 on Single Board Dimensions
0,50 to 100,50 on Single Board Dimensions
97,1.9 to 100,50 on Single Board Dimensions
0,0 to 1.9,3 on Single Board Dimensions
0,0 to 0,50 on Single Board Dimensions
0,0 to 0,50 on Single Board Dimensions
0,50 to 1.9,47 on Single Board Dimensions
3,3 to 5.6,4.3 on Single Board Dimensions
0,0 to 0,50 on Panel Dimension
0,50 to 100,50 on Panel Dimension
